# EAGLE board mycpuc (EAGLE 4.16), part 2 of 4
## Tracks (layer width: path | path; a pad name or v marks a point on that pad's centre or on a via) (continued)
+5V  (via drill 0.3 pad 0.3, 0.3 pad 0.81) (continued)
  Bottom 0.254: 153.55,53.21 R86.1 | 156,54.54 156,54.56 | 156,54.54 R85.1 | 156,53.21 156,54.54 | 157.5,60.01 155.95,60.01 155.95,60.03 R88.1 157.5,60.03 | 157.5,62.56 155.95,62.56 155.95,62.51 R87.1 157.5,62.51 | 157.5,65.01 155.95,65.01 155.95,65.02 R89.1 157.5,65.02 | 157.5,67.51 155.95,67.51 R90.1 157.5,67.53 | 157.5,70.01 R91.1 157.5,70.02 | 147.65,72.26 147.63,72.28 R92.1 | 14.5,26.01 14.44,25.95 R47.1 | R48.1 19,24.51 19.05,24.56 | R46.1 18.96,22.1 18.98,22.08 19,22.06 | R44.1 19,19.61 18.96,19.65 | R42.1 | 18.98,23.31 14.43,23.31 R45.1 | 18.96,20.81 R43.1 | 18.95,18.31 14.46,18.31 R41.1 | 113.58,30.96 IC15.26 | 111.05,28.81 111.55,28.31 113.55,28.31 IC15.22 | v110.45,29.56 110.5,29.36 111.05,28.81 | IC15.23 113.58,29.01 112.3,29.01 112.1,28.81 111.05,28.81 | v88.9,45.06 88.6,44.76 88.6,40.56 89.1,40.06 89.1,39.01 R84.2 | J1.A30 7.8,84.3 7.8,84.31 | 7.8,84.31 R38.2 | J1.C30 7.8,84.3 7.8,84.31 | R52.2 6.71,78.42 6.3,78.01 4.7,78.01 4,78.71 4,82.96 J1.A30 | J1.A30 | J1.A30 | R67.1 113.55,91.81 113.52,91.84 R117.2 | R121.2 141.92,66.94 v141.55,67.31 | R123.2 143.33,59.98 v143.35,60.01 143.35,59.96 143.4,60.01 144.4,60.01 144.85,59.56 144.85,54.86 144.48,54.49 R124.2 | C103.2 114.35,67.86 114.34,67.87 | R145.2 116.15,83.31 | R144.2 118.72,83.29 118.7,83.31 118.68,83.29 | R141.2 97.9,81.21 98.25,81.56 | 92.7,78.91 v92.65,78.91 92.7,78.86 | v64.65,96.56 64.63,96.58 | 64.6,95.31 v64.65,95.36 | D25.2 62.98,95.28 63,95.26 63.05,95.31 | R116.2 68.34,96.46 69.45,96.46 69.75,96.76 69.85,96.76 v69.85,96.81
  Bottom 0.305: R67.1 113.52,84.84 115.05,83.31 116.15,83.31 | R145.2 118.68,83.29 | R142.2 98.93,82.84 98.25,82.16 98.25,81.56 | 97.9,81.21 96.75,81.21 96,80.46 94.25,80.46 92.7,78.91 | R143.2 92.36,78.52 92.7,78.86
  Bottom 0.35: IC16.26 89.6,10.45 89.75,10.46 91.85,10.46
  Bottom 0.406: 157.5,60.01 157.5,53.56 157.15,53.21 156,53.21 153.55,53.21 153.55,52.46 v153.6,52.41 153.65,52.36 | 157.5,60.03 157.5,62.56 | 157.5,62.51 157.5,65.01 | 157.5,65.02 157.5,67.51 | 157.5,67.53 157.5,70.01 | 157.5,70.02 157.5,71.31 157.05,71.76 150.85,71.76 149,73.61 148,73.61 147.65,73.26 147.65,72.26 | 16.65,26.01 18.8,26.01 19.05,25.76 19.05,24.56 | 16.65,26.01 14.5,26.01 | 18.98,22.08 18.98,23.31 R48.1 | 18.96,19.65 18.96,20.81 R46.1 | R42.1 18.95,18.31 R44.1 | R102.1 120.86,12.85 120.85,13.01 118.35,13.01 | 105.65,13.01 103.25,13.01 103.1,12.86 103.1,11.56 R95.1 | 105.65,13.01 105.7,13.01 105.69,13 R96.1 | 108.2,13.01 110.75,13.01 | 110.75,13.01 113.25,13.01 | 113.25,13.01 115.8,13.01 | 115.8,13.01 118.35,13.01 | R97.1 108.19,13 108.2,13.01 | R98.1 110.74,13 110.75,13.01 | R99.1 113.24,13 113.25,13.01 | R100.1 115.79,13 115.8,13.01 | R101.1 118.36,13 118.35,13.01 | J1.C8 15.13,28.42 16.65,26.91 16.65,26.01 | v16.4,60.01 14.75,60.01 C57.1 | 105.65,13.01 108.2,13.01 | 113.58,30.96 111,30.96 110.45,30.41 v110.45,29.56 | J10.20 | 92.35,8.51 92.35,8.11 92.08,7.84 IC16.22 89.59,7.84 87.46,7.84 v86.85,8.46 86.95,8.51 89.65,8.51 | 92.35,8.51 92.35,9.96 91.85,10.46 | IC16.23 89.6,8.51 89.65,8.51 | 89.65,8.51 92.35,8.51 | 141.5,67.26 v141.55,67.31 143.21,68.97 R83.2 | v142.1,96.76 142.35,96.76 142.13,96.78 | L6.2 68.2,67.76 68.23,67.73 | C61.1 67.57,69.93 67.55,69.91 67.6,69.86 | R134.2 136.12,11.33 136.1,11.31 R135.2 R136.2 | R136.2 133.7,11.31 | R136.2 R137.2 | R137.2 131.3,11.36 | R138.2 R137.2 | R138.2 128.95,11.31 | R138.2 126.62,11.33 126.6,11.31 R139.2 | 113.3,67.87 R151.2 | 113.3,67.87 114.34,67.87 | v118.15,68.31 118.15,68.81 117.4,69.56 113.8,69.56 113.3,69.06 113.3,67.87
  Bottom 0.406: IC24.8 113.62,65.58 113.3,65.56 113.3,67.87 | 64.63,96.58 64,97.21 63.1,97.21 D25.1 | v64.65,95.36 v64.65,96.56 | 63.05,95.31 64.6,95.31
  Bottom 0.61: 120.85,13.01 122.15,13.01 123.45,11.71 123.45,11.31 | 142.35,96.76 v143.1,96.76 | L3.2 142.13,96.78 | 123.45,11.31 J10.20 | 123.45,11.31 126.6,11.31
  Bottom 0.813: 68.23,67.73 L2.2 | L6.2 68.21,68.5 67.6,69.11 67.6,69.86 | v67.75,91.71 v68.55,91.71 v69.35,91.71 | v105.8,42.33 105.8,43.38 105.78,43.41 | 8.3,28.36 8.3,28.41 v8.3,30.76 | 7.2,28.41 v7.2,30.76 | J1.C8 10.42,28.41 10.4,28.41 12.15,28.41 v12.15,30.36
  Bottom 1.016: 68.15,67.81 68.18,67.78 L6.2 | R158.2 112.38,43.41 105.78,43.41
  Bottom 1.27: v67.75,91.71 64.95,88.91 64.95,78.01 66.35,76.61 66.35,74.16 65.45,73.26 65.45,68.51 66.15,67.81 68.15,67.81 | J1.C8 10.4,28.41 8.3,28.41 7.2,28.41 5.35,28.41
  other vias: 105.8,43.41
  pour Route15 (isolate 0.254): 0.2,0.41 0.25,9.11 0.25,99.66 18.15,99.66 18.15,38.26 18.85,37.61 19.85,37.61 19.85,35.16 15.65,31.01 15.65,14.91 41.65,14.91 41.65,16.11 48.35,16.11 48.35,9.06 74.2,9.06 74.2,20.18 87.3,33.28 87.3,91.16 67.15,91.16 62.4,95.91 50.15,95.91 50.2,95.91 18.55,95.91 18.55,99.66 159.75,99.66 159.8,0.41
-5V
  Bottom 0.254: 108.24,91.62 108.25,91.61 | 108.24,91.62 R67.3 | 108.32,91.69 108.24,91.62 | 105.45,88.91 D26.A
  Bottom 0.305: C85.1 105.34,91.72 105.45,91.56 105.45,88.91 | D26.A 105.53,88.94 105.45,88.91 | R148.1 105.45,88.91
  Bottom 0.406: C85.1 108.32,91.69
-10V  (via drill 0.3 pad 0.81)
  Top 0.254: D14.2 108.93,31.13 108.9,31.16 D14.1 108.8,31.46 107.65,32.61 107.65,33.06 107.48,33.29 D15.1 105.52,33.29 105.51,33.3 | 105.51,33.3 105.8,33.36 105.55,33.36 105.55,34.31 103.25,36.61 98.05,36.61 v97.8,36.91 | 105.51,33.3 D15.2
  Bottom 0.254: v97.8,36.91 97.8,36.86
  Bottom 0.305: v97.8,36.91 97.8,53.96 99.65,55.81 99.65,60.51 103.65,64.51 103.65,76.96 104.3,77.61 105.7,77.61 106.2,78.11 106.2,79.96 105.45,80.71 R148.2
/B_WR
  Bottom 0.254: 10.42,33.49 10.45,33.46 | 10.42,33.49 J1.C10 | 10.42,33.49 10.43,33.49 10.8,33.86 10.85,33.86 11,34.01 12.45,34.01 12.48,34.04 R49.2
/BUS_RDC
  Top 0.254: IC9.6 13.43,34.74 10.9,32.21 6.5,32.21 5.3,31.01 J1.A9
/BUS_RDD  (via drill 0.3 pad 0.81)
  Top 0.254: J1.C9 10.64,30.96 10.65,30.96 13.78,34.09 IC9.7 | v98.25,57.01 98.25,56.76 101.2,53.81 102.45,53.81 103.3,54.66 IC23.11
  Route15 0.203: v98.25,57.01 97,57.01 94.7,59.31 94.7,64.51 82.8,76.41 49.1,76.41 48.15,75.46 42.85,75.46 42.75,75.51 25.2,75.51 18.35,68.66 15.55,68.66 14.45,67.56 14.45,40.76 11.05,37.36 9.75,37.36 9.15,36.76 9.15,32.26 10.46,30.96 J1.C9
/BUS_WR  (via drill 0.3 pad 0.81)
  Top 0.254: IC9.8 15,33.46 v16.3,33.46
  Bottom 0.254: R49.1 15.72,34.04 v16.3,33.46 16.32,33.44 R146.1
/INT.RES  (via drill 0.3 pad 0.81)
  Top 0.254: v17.45,85.11 16.2,85.11 12.9,81.81 10.5,81.81 10.45,81.76 10.44,81.76 J1.C29 | IC23.99 107.03,62.73 106.8,62.96 104.65,62.96 v104.25,62.56
  Route15 0.203: v17.45,85.11 17.45,85.16 23,85.16 23.45,85.61 37.45,85.61 42.3,90.46 48.25,90.46 49,89.71 62.65,89.71 65.75,86.61 76.8,86.61 80.85,82.56 85.65,82.56 102.75,65.46 102.75,64.01 v104.25,62.56
  Bottom 0.254: J1.C29 10.44,81.76 10.45,81.76 9.01,80.32 R52.1 | v17.45,85.11 22.75,85.11 24.55,86.91 35.95,86.91 36.5,87.46 36.5,90.16 37.19,90.85 T1.3
A0  (via drill 0.3 pad 0.81)
  Top 0.203: IC7.10 13.69,43.15 13.35,42.81 13.35,40.21
  Top 0.254: 13.35,40.21 11.75,38.61 10.4,38.61 J1.C12 | v96.9,58.41 98.2,58.41 100.95,55.66 IC23.9
  Route15 0.203: J1.C12 10.45,38.56 13.75,41.86 13.75,67.96 15.1,69.31 17.95,69.31 24.9,76.26 41.1,76.26 42.85,78.01 48.25,78.01 49.1,77.16 83.15,77.16 95.5,64.81 95.5,59.81 v96.9,58.41
A1  (via drill 0.3 pad 0.81)
  Top 0.203: IC7.9 13.54,43.8 12.8,43.06 12.8,40.91 11.75,39.86
  Top 0.254: J1.A12 6.6,39.86 11.75,39.86 | IC23.8 101.7,56.16 v101.25,56.61
  Route15 0.203: 5.35,38.57 5.35,38.56 | J1.A12 5.35,38.57 | 5.35,38.57 5.35,38.61 7.05,40.31 7.05,41.56 7.3,41.81 7.3,75.56 9.7,77.96 13.9,77.96 16.75,80.81 22.35,80.81 24.8,83.26 38.25,83.26 43.6,88.61 47.15,88.61 47.9,87.86 61.35,87.86 64.85,84.36 75.9,84.36 79.85,80.41 84.45,80.41 99.2,65.66 99.2,63.46 99.8,62.86 99.8,58.11 101.25,56.66 v101.25,56.61
A2  (via drill 0.3 pad 0.81)
  Top 0.203: IC7.8 13.34,44.45 12.25,43.36 12.25,41.91 11.5,41.16
  Top 0.254: J1.C13 10.4,41.16 11.5,41.16 | IC23.6 102.75,57.16 v102.65,57.26
  Route15 0.203: J1.C13 10.4,41.11 | J1.C13 | J1.C13 11.7,42.41 11.7,72.26 12.5,73.06 18.25,73.06 25.7,80.51 47.65,80.51 48.9,81.76 60,81.76 60.4,82.16 74.95,82.16 78.8,78.31 83.15,78.31 96.45,65.01 96.45,60.21 100.95,55.71 101.95,55.71 102.65,56.41 v102.65,57.26
A3  (via drill 0.3 pad 0.81)
  Top 0.203: IC7.7 13.09,45.1 11.7,43.71 11.7,43.06 11.1,42.46
  Top 0.254: J1.A13 5.35,41.11 6.7,42.46 11.1,42.46 | IC23.4 102.5,58.16 v101.35,59.31
  Route15 0.203: J1.A13 5.35,41.11 6.65,42.41 6.65,77.53 9.6,80.46 13.1,80.46 14.2,81.56 21.95,81.56 24.45,84.06 37.95,84.06 43.1,89.21 47.55,89.21 48.3,88.46 61.85,88.46 65.2,85.11 76.25,85.11 80.2,81.16 84.8,81.16 101.25,64.76 101.25,59.41 v101.35,59.31
A4  (via drill 0.3 pad 0.76, 0.3 pad 0.81)
  Top 0.254: IC23.97 108.03,62.58 106.9,63.71 103.2,63.71 101.85,62.36 v98.55,62.36 | v16.5,45.48 16.5,45.51 16.26,45.75 IC7.6
  Route2 0.254: v8.88,47.41 8.97,47.51 14.47,47.51 v16.5,45.48
  Route15 0.203: v98.55,62.36 98.35,62.56 98.35,65.36 84.05,79.66 79.6,79.66 75.6,83.66 64.5,83.66 60.9,87.26 48.95,87.26 47.3,85.61 41.85,85.61 38.65,82.41 25.1,82.41 20.4,77.71 16.05,77.71 13.8,75.46 9.75,75.46 7.95,73.66 7.95,48.36 8.88,47.43 v8.88,47.41
  Bottom 0.254: R147.2 8.26,46.99 8.68,47.41 v8.88,47.41
A4B
  Bottom 0.254: R147.1 8.26,43.35 8.47,43.13 10.12,43.13 10.47,43.48 10.43,43.68 10.44,43.66 | 10.44,43.66 10.45,43.66 | 10.44,43.66 J1.C14
A5  (via drill 0.3 pad 0.81)
  Top 0.254: IC7.5 12.34,46.4 10.85,44.91 6.6,44.91 5.36,43.66 J1.A14 | IC23.22 103,49.16 101.9,48.06 99.9,48.06 97.8,50.16 97.8,55.66 92.95,60.51 v92.95,60.96
  Route15 0.203: v92.95,60.96 92.95,63.96 81.85,75.06 66.9,75.06 65.6,73.76 52.6,73.76 49.2,70.36 40.25,70.36 37.15,67.26 37.15,65.76 36.15,64.76 26.15,64.76 25,63.61 25,56.61 20.55,52.16 20.55,36.16 13.55,29.21 11.65,29.21 11.1,29.76 4.5,29.76 3.7,30.56 3.7,41.98 5.33,43.61 5.34,43.62 J1.A14
A6
  Top 0.254: IC7.4 11.84,47.05 11,46.21 10.45,46.21 10.45,46.2 J1.C15
A7
  Top 0.203: 9.05,48.48 10.03,47.51
  Top 0.254: IC7.3 11.49,47.7 11.3,47.51 10.03,47.51 | J1.A15 7.65,48.48 9.05,48.48
A8  (via drill 0.3 pad 0.81)
  Top 0.203: IC8.10 13.81,54.17 13.4,53.76 13.4,51.61 10.55,48.76 10.45,48.76
  Top 0.254: 10.45,48.76 10.44,48.74 J1.C16 | IC23.3 103.45,58.66 101.6,60.51 v97.45,60.51
  Route15 0.203: v97.45,60.51 97.45,65.11 83.65,78.96 79.25,78.96 75.25,82.96 64.15,82.96 60.45,86.66 49.55,86.66 48.1,85.21 48.1,83.66 47.4,82.96 40.45,82.96 39.1,81.61 25.5,81.61 17.7,73.81 12.2,73.81 11.3,72.91 9.5,72.91 8.6,71.96 8.6,50.56 10.2,48.96 10.43,48.76 J1.C16
A9  (via drill 0.3 pad 0.81)
  Top 0.203: IC8.9 13.66,54.82 12.8,53.96 12.8,51.91 10.95,50.06 10.9,50.06
  Top 0.254: J1.A16 6.65,50.06 10.9,50.06 | IC23.1 103.55,59.66 102.8,60.41 v102.8,60.86
  Route15 0.203: J1.A16 3.9,50.21 3.9,82.56 4.35,83.01 12.55,83.01 13.7,84.16 23.35,84.16 24.05,84.86 37.7,84.86 42.7,89.86 47.9,89.86 48.7,89.06 62.3,89.06 65.55,85.81 76.6,85.81 80.55,81.86 85.25,81.86 101.95,65.16 101.95,61.71 v102.8,60.86
A10
  Top 0.203: IC8.8 13.51,55.47 12.2,54.16 12.2,52.66 10.85,51.31 10.45,51.31
  Top 0.254: 10.45,51.31 J1.C17
A11
  Top 0.203: IC8.7 13.36,56.12 11.65,54.41 11.65,53.26 10.95,52.56 10.9,52.56
  Top 0.254: J1.A17 6.6,52.56 10.9,52.56
A12
  Top 0.203: IC8.6 13.21,56.77 10.45,54.01
  Top 0.254: 10.43,53.82 10.45,53.81 | J1.C18 10.43,53.82 | 10.43,53.82 10.45,54.01
A13
  Top 0.203: IC8.5 13.06,57.42 10.75,55.11 10.7,55.11
  Top 0.254: J1.A18 5.35,53.81 6.65,55.11 10.7,55.11
A14
  Top 0.254: IC8.4 12.66,58.07 10.95,56.36 10.45,56.36 10.44,56.36 J1.C19
A15
  Top 0.254: IC8.3 12.26,58.72 11.2,57.66 6.65,57.66 J1.A19
ADDR0  (via drill 0.3 pad 0.76, 0.3 pad 0.81)
  Top 0.203: 41.02,80.98 41.02,80.99 IC10.1
  Top 0.254: IC21.P15 51.99,44.75 50.45,43.21 50.45,41.96 47.1,38.61 46.6,38.61 46.57,38.58 J4.21 | IC7.14 18.94,42.5 v18.75,42.31 | IC11.1 41,96.06 40.87,95.93 40.87,89.81 41.83,88.86 41.83,84.18 41.02,82.98 41.02,80.98 41.02,76.73 42.35,75.41 42.35,66.46 v41.65,65.76
  Route2 0.203: 41.8,65.61 v41.65,65.76 | J4.21 46.58,38.61 46.7,38.61
  Route2 0.254: 41.8,65.61 42.2,65.16 42.2,63.41 42.9,62.71 48.1,62.71 51.6,59.21 51.6,44.71 50.4,43.51 50.4,42.31 46.7,38.61
  Route15 0.254: v38.95,38.06 38.95,38.01 39,37.96 40.7,37.96 41.05,38.31 42.25,38.31 43.25,37.31 44.85,37.31 46.1,38.56 46.55,38.56 J4.21
  Bottom 0.203: IC12.45 34.88,68.74 35.7,69.56 37.95,69.56 41.65,65.86 v41.65,65.76
  Bottom 0.254: v38.95,38.06 37.8,39.21 22.4,39.21 19.3,42.31 v18.75,42.31
ADDR1  (via drill 0.3 pad 0.76, 0.3 pad 0.81)
  Top 0.152: 40.4,84.01 40.4,87.26 | 40.4,69.26 40.4,72.41
  Top 0.203: IC7.15 20.29,43.15 20.25,43.11 v17.65,43.11 | 40.4,84.01 39.75,83.01 39.75,82.28 | 39.75,80.98 | 39.75,80.98 IC10.2 | 39.75,82.28 39.75,80.98 | 39.75,82.28 39.75,76.21 40.4,75.21 40.4,72.41 | v41.1,64.71 41.1,64.96 40.8,65.26 40.8,68.51 40.4,69.26
  Top 0.254: IC21.P14 51.49,45.25 49.65,43.41 49.65,42.26 47.25,39.86 45.95,39.86 44.7,38.61 43.95,38.61 43.98,38.58 J4.22 | IC11.2 39.75,89.66 40.4,89.01 40.4,87.26
  Route2 0.203: v21.8,62.46 21.8,60.96 16.7,55.86 v16.65,55.86
  Bottom 0.203: v17.65,43.11 19.35,43.11 | 24.9,64.26 24.88,64.28 IC12.25 | v41.1,64.71 40.6,65.21 40.6,66.01 37.7,68.91 35.85,68.91 35.4,68.46 35.4,67.66 37.4,65.66 37.4,62.31 37,61.91 30.75,61.91 27.8,58.96 | v21.8,62.46 22.05,62.41
  Bottom 0.254: J4.22 44,38.61 43.9,38.71 43.4,39.16 42.75,39.16 42.1,39.81 22.65,39.81 19.35,43.11 | v17.65,43.11 17.05,43.11 15.57,44.58 15.57,54.78 v16.65,55.86 | 27.8,58.96 26.95,58.96 24.9,61.01 24.9,62.41 | 22.05,62.41 24.9,62.41 | 24.9,62.41 24.9,64.26
ADDR2  (via drill 0.3 pad 0.76, 0.3 pad 0.81)
  Top 0.152: 39.12,84.01 39.12,87.28 | 39.1,69.31 39.1,72.41
  Top 0.203: IC7.16 18.86,43.8 v18.75,43.91 | 39.12,84.01 38.48,83.01 38.48,81.01 38.48,81 | 38.48,81 38.5,80.98 | 38.48,81 IC10.3 | 38.48,81 38.48,76.03 39.1,75.01 39.1,72.41 | v38.9,63.96 38.9,64.26 39.7,65.06 39.7,68.31 39.1,69.31
  Top 0.254: IC21.P13 50.99,45.75 48.8,43.56 48.8,42.86 47.05,41.11 47.04,41.12 J4.23 | IC11.3 38.48,89.65 39.12,89.01 39.12,87.28 | IC7.16 22.94,43.8 v24,44.86
  Route2 0.203: 38.9,63.76 v38.9,63.96 | 46.65,41.16 46.61,41.12 J4.23
  Route2 0.254: 38.9,63.76 42.35,60.31 49.3,60.31 50.75,58.86 50.75,45.01 49.5,43.76 49.5,42.66 48,41.16 46.65,41.16
  Bottom 0.203: 24.88,44.83 IC12.24
  Bottom 0.254: J4.23 45.39,39.96 43.1,39.96 42.65,40.41 22.9,40.41 19.4,43.91 v18.75,43.91 | v24,44.86 24.88,44.83
ADDR3  (via drill 0.3 pad 0.76, 0.3 pad 0.81)
  Top 0.152: 37.85,84.01 37.85,87.28 | 37.85,69.11 37.85,72.41
  Top 0.203: v17.65,44.46 17.9,44.71 19.1,44.71 19.36,44.45 IC7.17 20.94,44.45 20.95,44.46 22.45,44.46 25.1,47.11 v25.1,47.26 | 37.85,84.01 37.23,82.98 37.23,81.03 | 37.23,81.03 37.21,81 IC10.4 | 37.23,81.03 37.2,80.96 37.33,80.83 37.33,75.83 37.85,74.96 37.85,72.41 | v38.35,66.96 38.4,66.96 38.1,67.21 38.1,68.61 37.85,69.11
  Top 0.254: IC21.P12 50.49,46.25 48,43.76 48,43.11 47.3,42.41 46.05,42.41 44.7,41.06 44.1,41.06 44.04,41.12 J4.24 | IC11.4 37.21,89.67 37.85,89.01 37.85,87.28
  Route2 0.203: J4.24 44.09,41.12
  Route2 0.254: v38.35,66.96 41.75,66.96 43.5,65.21 47.8,65.21 48.3,64.71 48.3,63.86 52.45,59.71 52.45,45.11 53.45,44.11 53.45,42.11 48.6,37.26 45.9,37.26 45.3,37.86 45.3,39.91 44.09,41.12
  Bottom 0.203: v17.65,44.46 17.9,44.71 19.45,44.71 | IC12.23 25.38,46.99 v25.1,47.26
  Bottom 0.254: 19.45,44.71 23.14,41.02 43.84,41.02 44,41.06 44.01,41.07 J4.24
ADDR4  (via drill 0.3 pad 0.76, 0.3 pad 0.81)
  Top 0.152: 36.58,84.01 36.58,87.31 | 36.6,69.11 36.6,72.38
  Top 0.203: v18.75,45.51 19.1,45.51 19.51,45.1 IC7.18 20.86,45.1 20.9,45.06 22.3,45.06 24.25,47.01 24.25,47.56 24.95,48.26 25.5,48.26 v25.65,48.36 | 36.58,84.01 35.95,83.01 IC10.5 | IC10.5 | IC10.5 | IC10.5 35.95,81.01 36.15,80.81 36.15,79.31 36.25,79.21 36.25,75.61 36.6,75.01 36.6,72.38 | 36.6,69.11 37,68.41 37,66.06 34.85,63.91 34.85,63.26
  Top 0.254: J4.25 46.9,43.66 49.99,46.75 IC21.P11 | IC11.5 35.94,89.64 36.58,89.01 36.58,87.31 | v34.8,63.21 34.85,63.26
  Route2 0.203: J4.25 46.55,43.71
  Route2 0.254: v34.8,63.21 34.8,62.71 40.05,57.51 47.3,57.51 47.85,56.96 47.85,45.01 46.55,43.71
  Bottom 0.203: IC12.22 25.88,48.19 v25.65,48.36
  Bottom 0.254: J4.25 45.3,42.41 43.05,42.41 42.25,41.61 23.4,41.61 19.5,45.51 v18.75,45.51
ADDR5  (via drill 0.3 pad 0.76, 0.3 pad 0.81)
  Top 0.152: 25.15,84.01 25.15,87.31
  Top 0.203: v17.65,46.56 17.9,46.31 19.2,46.31 19.76,45.75 IC7.19 20.89,45.75 20.9,45.76 22.25,45.76 23.65,47.16 23.65,48.06 v24.7,49.11 | 25.15,84.01 24.5,83.01 24.5,81.01 | 24.5,81.01 IC10.14 | 24.5,81.01 24.5,75.96 25.15,74.96 v25.15,72.81
  Top 0.254: IC21.P10 49.49,47.25 47.2,44.96 46.05,44.96 44.7,43.61 44,43.61 44.01,43.62 J4.26 | IC11.14 24.51,89.65 25.15,89.01 25.15,87.31
  Route2 0.203: v25.15,72.81 25.15,72.76 23.55,72.76 18.35,67.56 18.35,64.91 19.35,63.91 19.35,60.16 16.7,57.51 16.1,57.51 15.2,56.61 15.2,55.21 16.05,54.36 17.8,54.36 20.2,51.96 20.2,50.93 22.12,49.01 24.55,49.01 24.65,49.11 v24.7,49.11
  Bottom 0.203: v17.65,46.56 17.9,46.31 19.55,46.31 | IC12.21 26.38,47.79 26.5,47.91 26.5,48.81 26.1,49.21 | v24.7,49.11 24.8,49.21
  Bottom 0.254: J4.26 43.25,43.66 41.8,42.21 23.65,42.21 19.55,46.31 | 24.8,49.21 26.1,49.21
ADDR6  (via drill 0.3 pad 0.76, 0.3 pad 0.81)
  Top 0.152: 23.9,84.01 23.9,87.26 | 23.85,72.43 23.85,69.61 24.3,69.16
  Top 0.203: v18.75,47.11 18.8,47.06 19.2,47.06 19.86,46.4 IC7.20 20.81,46.4 20.8,46.41 22.15,46.41 23.1,47.36 23.1,49.26 23.7,49.86 v23.8,49.86 | 23.9,84.01 23.23,83.01 23.23,81.01 | 23.23,81.01 IC10.15 | IC10.15 | 23.23,81.01 23.23,75.88 23.85,74.86 23.85,72.43 | 24.3,69.16 24.3,64.96 v24,64.66
  Top 0.254: J4.27 46.89,46.2 48.94,48.25 IC21.P8 | IC11.15 23.24,89.69 23.9,89.03 23.9,87.26
  Route2 0.203: v24,64.66 24,68.76 23.45,69.31 20.95,69.31 18.9,67.26 18.9,65.21 19.95,64.16 19.95,59.91 16.95,56.91 16.3,56.91 15.8,56.41 15.8,55.46 16.3,54.96 18.15,54.96 20.85,52.26 20.85,51.13 22.27,49.71 23.6,49.71 v23.8,49.86
  Bottom 0.203: IC12.20 26.88,47.44 27.05,47.61 27.05,49.11 26.15,50.01
  Bottom 0.254: J4.27 45.31,44.96 43.5,44.96 41.35,42.81 23.9,42.81 19.6,47.11 v18.75,47.11 18.7,47.11 | v23.8,49.86 23.95,50.01 26.15,50.01
ADDR7  (via drill 0.3 pad 0.76, 0.3 pad 0.81)
  Top 0.152: 22.62,84.01 22.62,87.31 | 22.6,68.86 22.6,72.41
  Top 0.203: v17.65,47.91 19.1,47.91 19.96,47.05 IC7.21 20.76,47.05 20.75,47.06 22.05,47.06 22.55,47.56 22.55,50.21 v22.8,50.46 | 22.62,84.01 21.98,83.01 21.98,81.01 | 21.98,81.01 IC10.16 | 21.98,81.01 21.98,75.88 22.6,74.91 22.6,72.41
  Top 0.254: IC21.P7 48.44,48.75 47.15,47.46 45.95,47.46 44.7,46.21 44.1,46.21 44.09,46.2 J4.28 | IC11.16 21.97,89.66 22.62,89.01 22.62,87.31 | v22.95,68.51 22.6,68.86
  Route2 0.203: v22.95,68.51 21,68.51 19.5,67.01 19.5,65.41 20.15,64.76 20.85,64.76 22.75,62.86 22.75,61.06 21.5,59.81 21.5,51.36 22.4,50.46 v22.8,50.46
  Bottom 0.203: 24.15,43.41 41.1,43.41 43.89,46.2 | 43.89,46.2 43.85,46.21 | 43.89,46.2 J4.28 | v17.65,47.91 19.65,47.91 | 26.2,50.76 27.6,49.36 27.6,47.31 27.4,47.11 27.4,45.16 IC12.19
  Bottom 0.254: 19.65,47.91 24.15,43.41 | v22.8,50.46 23.1,50.76 26.2,50.76
ADDR8  (via drill 0.3 pad 0.76)
  Top 0.152: 21.32,84.01 21.32,87.31 | 21.35,69.16 21.35,72.41
  Top 0.203: 21.32,84.01 20.7,83.01 20.7,81.38 | IC10.17 20.7,75.81 21.35,74.81 21.35,72.41
  Top 0.254: J4.29 46.55,48.76 47.04,49.25 IC21.P6 | IC11.17 20.7,89.61 21.32,88.98 21.32,87.31 | 20.7,81.38 | IC10.17 20.7,81.38 | IC8.14 23.29,53.52 v29.1,47.71 | 21.35,69.16 21.35,67.91 v22.4,66.86
  Route2 0.203: 31.25,46.21 31.25,47.21 30.7,47.76 29.1,47.76 | v22.4,66.86 22.2,67.06 20.45,67.06 20.05,66.66 20.05,65.71 20.4,65.36 21.05,65.36 23.75,62.66 23.75,51.66 27.65,47.76 29.1,47.76 | 29.1,47.76 29.15,47.76 v29.1,47.71
  Route2 0.254: 31.25,46.21 31.65,45.81 38.8,45.81 40.6,47.61 45.45,47.61 46.55,48.71 J4.29
  Bottom 0.203: IC12.18 27.88,46.64 28.9,47.66 v29.1,47.71
ADDR9  (via drill 0.3 pad 0.76)
  Top 0.152: 20.07,84.01 20.07,87.36 | 20.05,69.21 20.05,72.41
  Top 0.203: 20.07,84.01 19.45,82.98 19.45,81.43 | IC8.15 26.89,54.17 31.95,49.11 31.95,46.96 v32.05,46.86 | IC10.18 19.43,75.73 20.05,74.71 20.05,72.41
  Top 0.254: IC21.P5 47.46,49.75 47.25,49.96 45.85,49.96 44.7,48.81 44.1,48.81 44.03,48.74 J4.30 | IC11.18 19.43,89.65 20.07,89.01 20.07,87.36 | 19.45,81.43 19.43,81.45 IC10.18 | 20.05,69.21 20.05,66.96 v20.85,66.21
  Route2 0.203: v20.85,66.21 21,66.21 24.3,62.91 24.3,51.96 25.9,50.36 30.85,50.36 31.95,49.26 31.95,46.91 32.05,46.81
  Route2 0.254: J4.30 40.63,48.74 38.7,46.81 32.05,46.81 v32.05,46.86
  Bottom 0.203: IC12.8 32.88,46.48 32.6,46.76 32.1,46.76 v32.05,46.86
ADDR10  (via drill 0.3 pad 0.76)
  Top 0.152: 20.07,79.53 20.07,82.98
  Top 0.203: IC11.20 20.7,84.03 20.07,82.98 | 20.07,79.53 20.07,75.81 20.7,74.81 20.7,70.81 20.7,67.46 21.7,66.46 21.7,65.76 21.35,65.41 20.4,65.41 18.95,63.96 18.95,62.86 17.7,61.01 17.7,56.81 19.7,54.81 20.8,54.81 20.81,54.82 IC8.16 27.04,54.82 32.8,49.06 v32.8,47.66
  Top 0.254: IC21.P4 48.21,50.25 47.15,51.31 46.6,51.31 46.57,51.28 J4.31 | 20.7,70.81 | 20.7,70.81 IC10.20
  Route2 0.254: J4.31 45.82,51.28 44.65,50.11 40.9,50.11 38.35,47.56 32.9,47.56 v32.8,47.66
  Bottom 0.203: IC12.7 33.38,47.08 v32.8,47.66
ADDR11  (via drill 0.3 pad 0.76)
  Top 0.152: 21.32,79.56 21.32,83.01
  Top 0.203: IC11.21 21.97,83.98 21.98,83.98 21.32,83.01 | 21.32,79.56 21.32,75.91 21.98,74.91 IC10.21 21.97,70.83 21.9,70.81 21.9,68.46 23.18,67.18 23.18,65.98 22.05,64.86 20.65,64.86 19.45,63.66 19.45,62.71 18.2,60.86 18.2,57.06 19.8,55.46 20.9,55.46 20.89,55.47 IC8.17 27.19,55.47 33.65,49.06 v33.65,48.36
  Top 0.254: IC21.P2 48.61,51.25 47.4,52.46 45.95,52.46 44.75,51.26 44.05,51.26 44.03,51.28 J4.32
  Route2 0.254: J4.32 41.02,51.28 38,48.26 33.75,48.26 v33.65,48.36 33.65,48.31
  Bottom 0.203: IC12.6 33.88,48.13 v33.65,48.36
ADDR12  (via drill 0.3 pad 0.76)
  Top 0.152: 22.6,79.58 22.6,83.01
  Top 0.203: IC11.22 23.24,84 22.6,83.01 | 22.6,79.58 22.6,75.91 23.23,74.91 23.23,70.91 23.25,70.88 | 23.25,70.88 IC10.22 | v34.55,49.11 34.35,49.11 27.34,56.12 IC8.18 20.89,56.12 | 23.25,70.88 23.25,69.41 23.75,68.91 23.75,65.71 22.35,64.31 20.85,64.31 19.95,63.41 19.95,62.51 18.7,60.66 18.7,57.31 19.8,56.21 20.8,56.21 20.89,56.12 | 20.89,56.12 20.9,56.11
  Top 0.254: IC21.P1 49.26,51.75 47.15,53.86
  Top 0.305: J4.33 46.55,53.86 47.15,53.86
  Route2 0.254: v34.55,49.11 34.55,49.06 | v34.55,49.11 37.75,49.11 41.25,52.61 45.25,52.61 46.5,53.86 46.55,53.86 J4.33 | v34.55,49.11 34.5,49.06
  Bottom 0.203: IC12.5 34.38,48.94 v34.55,49.11
ADDR13  (via drill 0.3 pad 0.76)
  Top 0.152: 23.9,79.61 23.9,83.01
  Top 0.203: IC11.23 24.51,84.02 23.9,83.01 | 23.9,79.61 23.9,75.81 24.35,75.06 24.35,70.83 | 24.35,70.83 24.51,70.84 IC10.23 | v35.35,49.91 34.35,49.91 27.49,56.77 IC8.19 20.81,56.77 20.8,56.76 20.75,56.81 19.95,56.81 19.2,57.56 19.2,60.46 20.45,62.31 20.45,63.11 21.15,63.81 24.4,63.81 24.85,64.26 24.85,69.36 24.5,69.71 24.5,70.11 | 24.35,70.83 24.35,70.36 24.6,70.11 24.5,70.11 | 24.5,70.11 24.45,70.11
  Top 0.254: IC21.P141 62.75,56.16 62.25,56.66 59.75,56.66 58.2,55.11 46,55.11 44.7,53.81 44.05,53.81 44.04,53.82 J4.34
  Route2 0.254: J4.34 41.41,53.82 37.45,49.86 35.35,49.86 v35.35,49.91
  Bottom 0.203: 34.88,48.09 IC12.4
  Bottom 0.254: 34.88,48.09 35.35,48.56 v35.35,49.91
ADDR14  (via drill 0.3 pad 0.76)
  Top 0.152: 25.15,79.63 25.15,83.01
  Top 0.203: IC11.24 25.78,84.01 25.15,83.01 | 25.15,79.63 25.15,76.06 25.95,74.86 25.95,70.86 25.75,70.86 IC10.24 25.78,68.74 25.4,68.36 25.4,63.96 24.7,63.26 21.4,63.26 20.95,62.81 20.95,62.16 19.7,60.26 19.7,57.81 20.05,57.46 20.85,57.46 IC8.20 27.64,57.42 34.3,50.76 v36.2,50.76
  Top 0.254: IC21.P140 63.25,56.66 62.55,57.36 59.35,57.36 58.35,56.36 46.6,56.36 46.55,56.41 J4.35
  Route2 0.254: J4.35 45.3,55.11 41.6,55.11 37.25,50.76 v36.2,50.76
  Bottom 0.203: 35.38,47.79 IC12.3
  Bottom 0.254: 35.38,47.79 36.2,48.61 v36.2,50.76
ADDR15  (via drill 0.3 pad 0.76, 0.3 pad 0.81)
  Top 0.152: 35.33,79.33 35.33,83.01
  Top 0.203: IC11.32 35.94,84 35.33,83.01 | IC10.32 35.92,70.88 35.95,71.26 36.02,71.33 36.02,74.91 35.75,75.38 35.75,78.91 35.33,79.33 | IC10.32 | IC8.21 21.3,58.06 21.39,58.02 27.85,58.02 | 27.85,58.02 34.09,51.77 35.26,51.77 35.3,51.81 v35.35,51.81 | 35.95,70.76 IC10.32 | v36.2,68.01 35.95,68.26 | 27.85,58.02 27.85,58.06 28.25,58.46 v28.55,58.46
  Top 0.254: IC21.P137 64.75,56.21 62.9,58.06 58.9,58.06 58.45,57.61 v49,57.61 | 35.95,68.26 35.95,70.76
  Route2 0.254: v35.35,51.81 37.2,51.81 41.8,56.41 43.95,56.41 J4.36
  Bottom 0.203: 35.88,47.49 IC12.2 | J4.36 44.05,56.36 | 36.2,67.86 v36.2,68.01
  Bottom 0.254: v49,57.61 49,56.61 47.5,55.11 45.3,55.11 44.05,56.36 | 35.88,47.49 37.05,48.66 37.05,51.36 36.6,51.81 v35.35,51.81 | 36.2,67.86 38,66.06 38,61.81 37.35,61.16 31.25,61.16 v28.55,58.46
ADDR16  (via drill 0.3 pad 0.76)
  Top 0.152: 36.6,79.66 36.58,79.68 36.58,83.01
  Top 0.203: IC11.33 37.21,84.02 36.58,83.01 | IC10.33 | 35.65,62.51 35.65,63.71 37.5,65.56 37.5,68.56 37.15,69.21 37.15,70.61 IC10.33 | IC10.33 37.2,74.96 36.8,75.71 36.8,79.46 36.6,79.66
  Top 0.254: IC21.P135 65.75,56.31 63.3,58.76 48.65,58.76 47.45,57.56 42.7,57.56 | 35.65,62.51 40.6,57.56 42.7,57.56 | v41.15,45.41 42.7,46.96 42.7,57.56
  Bottom 0.203: v41.15,45.41 41.1,45.41
  Bottom 0.254: IC12.1 36.38,45.24 36.4,45.41 v41.15,45.41
ADDR17  (via drill 0.3 pad 0.76)
  Top 0.152: 37.85,79.63 37.85,83.01
  Top 0.203: IC11.34 38.48,84.01 37.85,83.01 | 37.85,79.63 37.85,76.01 38.48,75.01 38.48,70.98 IC10.34 | 38.5,70.86 38.5,69.26 39.18,68.08 39.18,65.69 v36.55,63.06
  Top 0.254: IC21.P132 67.25,55.86 63.55,59.56 48.7,59.56 48.05,60.21 39.4,60.21 v36.55,63.06 | 38.5,70.86 38.49,70.86 IC10.34
  Bottom 0.254: IC12.48 36.38,63.29 v36.55,63.06
ADDR18  (via drill 0.3 pad 0.76)
  Top 0.152: 39.12,79.66 39.12,83.01
  Top 0.203: IC11.35 39.75,84.01 39.12,83.01 | 39.12,79.66 39.12,76.01 39.75,75.01 39.75,71.03 39.73,71.01 39.75,70.98 IC10.35 39.75,69.31 40.25,68.41 40.25,64.01
  Top 0.254: IC21.P131 67.75,56.36 63.8,60.31 49.55,60.31 47.25,62.61 41.4,62.61 v40,64.01 | v40,64.01 40.25,64.01 | 40.25,64.01 | v40,64.01 | v30.05,58.41 30.05,57.06 v32,55.11
  Bottom 0.203: IC12.17 28.38,46.14 28.8,46.56
  Bottom 0.254: v30.05,58.41 32.1,60.46 37.75,60.46 40,62.71 v40,64.01 | 28.8,46.56 29.15,46.56 32,49.41 v32,55.11
BUS_4MHZ  (via drill 0.3 pad 0.81)
  Top 0.254: IC9.10 16.68,32.14 17.3,32.76 17.3,35.06 v16.75,35.61
  Bottom 0.254: v16.75,35.61 16.75,35.56 15.83,36.48 R51.1
BUS_CLK  (via drill 0.3 pad 0.81)
  Top 0.254: IC9.9 13.68,32.79 12.9,32.01 v12.9,31.66
  Bottom 0.254: R50.2 7.97,32.24 8.15,32.06 9.35,32.06 9.6,32.26 12.3,32.26 v12.89,31.67 v12.9,31.66
  Bottom 0.305: v12.9,31.66 12.9,31.71 v12.89,31.67
BUSCKOUT
  Bottom 0.254: R50.1 7.97,35.89 7.8,36.06 J1.A11
BUSCLK
  Top 0.254: IC9.15 42.98,32.14 43.15,32.31 44.7,32.31 45.89,33.5 | 45.89,33.5 46.6,33.51 | 45.89,33.5 J4.17 46.69,33.5 46.7,33.51 48.85,33.51 50.1,34.76 50.1,35.71 54.14,39.75 IC21.P25
BUSY
  Top 0.254: IC23.90 111.53,66.73 103.85,74.41 102.25,74.41 101.15,75.51 101.15,77.56 99.89,78.82 J15.21
  Bottom 0.254: J15.21 99.82,78.84 R141.1
C_TCK  (via drill 0.3 pad 0.81)
  Top 0.254: IC23.48 117.53,53.18 v114,56.71
  Route15 0.254: J14.5 72.8,92.96 72.8,90.76 73.55,90.01 75.1,90.01 81.3,83.81 95.85,83.81 99.3,80.36 103,80.36 103.65,79.71 103.65,75.21 105.45,73.41 105.45,65.41 110.05,60.81 110.05,55.71 111.8,53.96 112.75,53.96 114.05,55.26 114.05,56.66 v114,56.71
C_TDI  (via drill 0.3 pad 0.81)
  Top 0.254: v112.25,54.86 112.3,54.86 116.03,51.13 IC23.45
  Route15 0.254: J14.4 75,90.76 75.5,90.76 81.6,84.61 97.4,84.61 100.6,81.41 104.4,81.41 106.2,79.61 106.2,65.66 110.85,61.01 110.85,56.61 112.2,55.26 112.2,54.81 | 112.2,54.81 112.2,54.76 | v112.25,54.86 112.2,54.81
C_TDO  (via drill 0.3 pad 0.81)
  Top 0.254: IC23.83 115.03,62.98 114.7,63.31 114.7,70.41 v114.45,70.66
  Route15 0.254: J14.6 70.05,93.16 70.05,95.06 70.6,95.61 74.7,95.61 75.25,95.06 75.25,93.66 75.9,93.01 77.55,93.01 78.25,92.31 78.25,90.26 82.15,86.36 99,86.36 101.7,83.66 107.25,83.66 111.25,79.66 111.25,73.91 114.5,70.66 v114.45,70.66
C_TMS  (via drill 0.3 pad 0.81)
  Top 0.254: IC23.47 117.03,51.88 v113.1,55.81
  Route15 0.254: J14.2 76.57,90.84 81.85,85.51 97.4,85.51 100.4,82.51 105.8,82.51 108.7,79.61 108.7,75.26 107,73.56 107,65.91 111.6,61.31 111.6,57.06 112.85,55.81 v113.1,55.81
CLK
  Top 0.254: IC21.P52 68.75,28.01 68.3,27.56 55.4,27.56 54.9,27.06 54.9,24.81 55.45,24.26 58.95,24.26 59.4,23.81 59.4,23.36 59.44,23.3 JP1.2
CLK4MHZ  (via drill 0.3 pad 0.81)
  Top 0.254: v88.9,46.36 88.8,46.61 88.42,46.99 IC14.14 | IC21.P26 54.74,39.25 51.45,35.96 v51.45,35.41 51.45,35.01 48.65,32.21 46,32.21 45.3,31.51 45.3,30.36 44.6,29.66 43.05,29.66 41.22,31.49 IC9.14
  Bottom 0.254: v88.9,46.36 88.75,46.36 87.75,45.41 87.75,36.31 90.05,34.01 90.05,32.46 85.95,28.41 85.75,28.21 84.85,28.21 82.55,25.91 74.2,25.91 71.7,23.41 71.7,18.41 69.1,15.76 67.9,15.76 65.25,13.11 65.25,12.41 62.75,9.91 54.45,9.91 51.25,13.11 51.25,35.16 51.4,35.31 51.4,35.41 | J4.52 44.03,76.68 45.35,77.96 47.5,77.96 47.9,77.56 52.85,77.56 56.25,74.21 56.25,40.26 51.4,35.41 | v51.45,35.41 51.4,35.41
D0  (via drill 0.3 pad 0.81)
  Top 0.254: IC6.10 13.77,21.18 10.85,18.26 10.45,18.26 10.44,18.26 J1.C4 | v101.5,49.01 101.8,49.01 102.95,50.16 IC23.20
  Route15 0.203: v101.5,49.01 101.55,49.01 101.25,48.76 97.5,48.76 86.75,59.51 86.75,60.41 78.7,68.46 71.3,68.46 70.75,67.91 61.7,67.91 52.05,58.26 52.05,55.81 48.6,52.36 48.6,51.11 47.5,50.01 41.8,50.01 37.2,45.41 37.2,37.06 32.4,32.26 30,32.26 21.05,23.26 16.15,23.26 11.15,18.26 10.45,18.26 10.44,18.26 J1.C4
  Bottom 0.254: R41.2 12.54,18.26 J1.C4
D1  (via drill 0.3 pad 0.81)
  Top 0.254: IC6.9 13.37,21.83 11.1,19.56 6.6,19.56 5.34,18.3 J1.A4 | IC23.18 103,51.16 101.8,49.96 100.75,49.96 v100.45,49.66
  Route15 0.203: v100.45,49.66 100.35,49.56 97.55,49.56 87.55,59.56 87.55,60.41 78.75,69.21 71,69.21 70.35,68.56 61.2,68.56 51.2,58.61 51.2,56.26 47.45,52.56 43.35,52.56 36.5,45.71 36.5,37.26 32.2,32.96 29.7,32.96 20.9,24.11 15.85,24.11 11.3,19.56 8.55,19.56 7.25,18.26 J1.A4
  Bottom 0.254: J1.A4 6.79,18.26 8.05,17.01 17.04,17.01 R42.2
D2  (via drill 0.3 pad 0.81)
  Top 0.254: IC6.8 12.97,22.48 11.3,20.81 10.45,20.81 10.45,20.8 J1.C5 | IC23.17 102.6,51.66 101.55,50.61 99.55,50.61 v99.3,50.36
  Route15 0.203: v99.3,50.36 97.6,50.36 88.3,59.66 88.3,60.51 78.9,69.86 70.7,69.86 70.05,69.21 60.6,69.21 50.4,59.01 50.4,57.51 48.1,55.21 42.8,55.21 42.2,54.56 42.2,52.41 35.8,46.01 35.8,37.56 31.9,33.66 29.45,33.66 20.8,25.01 15.7,25.01 11.5,20.81 10.45,20.81 10.45,20.8 J1.C5
  Bottom 0.254: R43.2 12.55,20.81 12.55,20.8 J1.C5
D3  (via drill 0.3 pad 0.81)
  Top 0.254: IC6.7 12.57,23.13 11.55,22.11 6.65,22.11 J1.A5 | IC23.16 101.7,52.16 v101.1,51.56
  Route15 0.203: v101.1,51.56 101.1,51.51 100.9,51.31 97.55,51.31 89.05,59.81 89.05,60.61 77.9,71.71 71.55,71.71 69.7,69.86 60.15,69.86 49.65,59.36 48.75,59.36 48.15,58.76 48.15,58.16 47.6,57.61 42.95,57.61 41.35,56.06 41.35,52.56 35.1,46.31 35.1,39.86 33.9,38.66 33.9,38.06 33.05,37.21 33.05,35.81 31.55,34.31 29.15,34.31 20.6,25.81 15.4,25.81 11.65,22.06 8.55,22.06 7.3,20.81 5.4,20.81 5.4,20.8 J1.A5
  Bottom 0.254: J1.A5 6.8,20.8 8.05,19.56 R44.2
D4  (via drill 0.3 pad 0.81)
  Top 0.254: J1.C6 10.49,23.34 10.92,23.78 IC6.6 | IC23.15 100.45,52.66 v100.15,52.36
  Route15 0.203: v100.15,52.36 99.8,52.01 97.75,52.01 89.8,59.96 89.8,60.71 78.1,72.41 71.25,72.41 69.5,70.66 57.7,70.66 47.25,60.21 41.65,60.21 33.9,52.46 31.9,52.46 28.3,48.86 28.3,43.86 23.2,38.76 23.2,33.01 18.8,28.61 17.05,28.61 11.8,23.36 10.45,23.36 10.44,23.34 J1.C6
  Bottom 0.254: R45.2 12.55,23.36 12.54,23.34 J1.C6
D5  (via drill 0.3 pad 0.81)
  Top 0.254: IC6.5 12.68,24.43 12.45,24.66 6.65,24.66 J1.A6 | IC23.14 100.85,53.16 100.65,53.36 99.35,53.36 v98.95,52.96
  Route15 0.203: v98.95,52.96 97.65,52.96 90.6,60.01 90.6,60.71 78.25,73.06 68.1,73.06 66.45,71.41 57.35,71.41 48.65,62.71 43.2,62.71 33.65,53.16 31.65,53.16 27.7,49.21 27.7,44.21 22.55,39.06 22.55,33.36 18.5,29.31 16.75,29.31 12,24.56 8.75,24.56 7.55,23.36 5.33,23.36 | 5.33,23.36 5.25,23.36 | J1.A6 5.33,23.36
  Bottom 0.254: J1.A6 6.71,23.34 8,22.06 17,22.06 17.05,22.11 17.06,22.1 R46.2
D6  (via drill 0.3 pad 0.81)
  Top 0.254: IC6.4 13.08,25.08 12.25,25.91 10.45,25.91 J1.C7 | IC23.13 105.75,53.66 v106.2,53.21
  Route15 0.203: v106.2,53.21 106.15,53.16 100.6,53.16 99.85,53.91 97.55,53.91 91.3,60.16 91.3,60.81 78.35,73.71 67.65,73.71 66.15,72.21 56.95,72.21 49.95,65.21 43.15,65.21 42.4,64.46 42.4,62.91 33.35,53.86 31.35,53.86 27.1,49.61 27.1,44.61 21.85,39.36 21.85,35.46 12.3,25.91 10.5,25.91 10.45,25.86 J1.C7
  Bottom 0.254: R47.2 12.53,25.88 J1.C7
D7  (via drill 0.3 pad 0.81)
  Top 0.254: IC6.3 13.48,25.73 12.05,27.16 6.65,27.16 5.35,25.86 5.34,25.87 J1.A7 | IC23.12 105.85,54.16 v106.2,54.51
  Route15 0.203: J1.A7 5.35,25.91 7.35,25.91 8.5,27.06 12.4,27.06 21.2,35.86 21.2,39.66 26.5,44.96 26.5,50.06 30.75,54.31 30.75,55.41 37.85,62.51 37.85,64.31 41.35,67.81 51.55,67.81 56.7,72.96 65.85,72.96 67.25,74.36 81.5,74.36 92,63.86 92,60.31 97.85,54.46 100.15,54.46 100.8,53.81 102.6,53.81 103.3,54.51 v106.2,54.51 106.25,54.51
  Bottom 0.254: J1.A7 6.67,25.88 7.9,24.66 17.05,24.66 17.05,24.59 R48.2
DA0
  Top 0.254: J12.35 130.9,61.36 130.85,61.36 | 130.85,61.36 127.75,61.36 125.95,59.56 125.95,56.86 123.75,54.66 IC23.65 | J13.35 139.76,61.36 130.85,61.36
DA1
  Top 0.254: J12.33 130.95,57.56 130.95,57.66 130.92,58.86 130.9,58.86 | 130.9,58.86 127.75,58.86 127.15,58.26 127.15,56.36 124.45,53.66 IC23.63 | J13.33 139.77,58.86 130.9,58.86
DA2
  Top 0.254: IC23.64 124.1,54.16 126.55,56.61 126.55,58.71 127.95,60.11 128.23,60.08 J12.36
  Route15 0.254: J12.36 129.57,58.96 137.2,58.96 138.4,60.16 138.4,60.17 J13.36
DATA0  (via drill 0.3 pad 0.76)
  Top 0.152: 34.02,84.01 34.02,87.26
  Top 0.203: 34.02,84.01 33.38,83.01 33.38,80.98 | 33.38,80.98 33.4,81.01 IC10.7 | v24.05,37.71 24.05,38.76 | 37.1,53.71 27.75,63.06 27.75,65.81 26.75,66.81 v26.75,67.41 | 33.38,80.98 33.5,80.96 33.5,77.56 v33.55,77.36
  Top 0.254: IC21.P36 57.84,34.25 57.35,33.76 57.35,32.46 52.65,27.76 52.65,25.31 48.05,20.71 46.55,20.71 46.5,20.76 J4.7 46.6,20.76 45.4,19.56 42.4,19.56 41.43,20.53 IC6.14 | IC11.7 33.4,89.63 34.02,89.01 34.02,87.26 | 24.05,38.76 29.1,43.81 30.75,43.81 37.1,50.21 37.1,53.71
  Bottom 0.203: 26.75,67.56 26.63,67.59 v26.75,67.41 26.75,67.46 | 26.75,67.46 26.75,67.31 26.88,67.18 IC12.29 | 26.75,67.46 26.75,67.56 | 26.75,67.56 26.75,67.71 25.95,68.51 25.95,78.81 27.3,80.16 32.6,80.16 | 33.4,77.61 33.5,77.46 v33.55,77.36
  Bottom 0.254: v24.05,37.71 24.05,30.81 35.4,19.51 45.25,19.51 J4.7 | 32.6,80.16 33.4,79.36 33.4,77.61
DATA1  (via drill 0.3 pad 0.76)
  Top 0.152: 32.77,84.01 32.77,87.28 32.88,87.41
  Top 0.203: 32.77,84.01 32.12,83.01 32.12,81.01 | 32.12,81.01 32.13,81.01 IC10.8 | v24.85,36.96 24.85,38.66 | 37.75,53.81 28.3,63.26 28.3,66.06 27.9,66.46 27.9,67.06 v27.85,67.21 | 32.12,81.01 32.12,79.03 v32.25,78.91
  Top 0.254: IC21.P35 57.24,34.75 56.65,34.16 56.65,32.86 51.9,28.11 51.9,25.76 48.3,22.16 45.9,22.16 44.56,20.82 44.01,20.82 J4.8 43.96,20.8 43.58,21.18 IC6.15 | IC11.8 32.13,89.48 32.88,88.73 32.88,87.41 | 24.85,38.66 29.4,43.21 31.05,43.21 37.75,49.91 37.75,53.81
  Bottom 0.203: IC12.31 27.88,67.33 27.85,67.36 | 27.85,67.36 27.85,67.46 26.6,68.76 26.55,68.86 26.55,78.56 27.55,79.56 31.6,79.56 32.15,79.01 32.15,78.96 v32.25,78.91 | v27.85,67.21 27.85,67.36
  Bottom 0.254: v24.85,36.96 24.85,31.11 35.15,20.81 44.05,20.81 44.04,20.8 J4.8
DATA2  (via drill 0.3 pad 0.76)
  Top 0.152: 28.98,84.01 28.95,84.03 28.95,87.31 | 28.95,89.06 28.93,89.06 | 29.3,69.16 28.95,69.51 28.95,72.33
  Top 0.203: 28.95,87.31 28.95,89.06 | 28.98,84.01 28.32,83.01 28.32,81.08 IC10.11 28.35,80.96 28.3,80.91 28.3,79.51 28.12,79.33 28.12,77.09 28.95,75.81 28.95,72.33 | v25.65,37.71 25.65,38.56 | 38.35,53.96 28.85,63.46 v28.85,66.71 29.3,67.16 29.3,69.16
  Top 0.254: IC21.P33 57.24,35.75 55.95,34.46 55.95,33.21 51.15,28.41 51.15,26.21 48.3,23.36 46.55,23.36 J4.9 46.55,23.26 46.5,23.21 45.75,23.21 44.57,22.03 41.67,22.03 41.45,21.81 20.95,21.81 IC6.16 | IC11.11 28.32,89.66 28.93,89.06 | 25.65,38.56 29.7,42.61 31.4,42.61 38.35,49.56 38.35,53.96
  Bottom 0.203: v28.85,66.71 28.85,66.81 28.88,66.78
  Bottom 0.254: 28.88,66.78 IC12.33 | v25.65,37.71 25.65,31.26 34.85,22.06 45.35,22.06 46.55,23.26 J4.9
DATA3  (via drill 0.3 pad 0.76)
  Top 0.152: 27.7,84.01 27.7,87.31
  Top 0.203: 27.7,84.01 27.05,83.01 IC10.12 | IC10.12 | IC10.12 27.05,81.01 26.95,80.91 26.95,76.66 27.75,75.36 27.75,73.71 27.8,73.66 v27.75,73.66 | v26.45,36.96 26.45,38.51 | 38.95,54.11 29.9,63.16 29.9,66.26 29.85,66.31 v29.85,66.21 29.85,68.46 v30.2,68.81
  Top 0.254: IC21.P32 56.79,36.25 55.25,34.71 55.25,33.56 50.4,28.76 50.4,26.71 48.4,24.66 45.8,24.66 44.5,23.36 43.95,23.36 43.97,23.34 J4.10 43.92,23.34 43.9,23.36 41.8,23.36 40.92,22.48 IC6.17 | IC11.12 27.05,89.66 27.25,89.46 27.25,87.76 27.7,87.31 | 26.45,38.51 29.95,42.01 31.7,42.01 38.95,49.26 38.95,54.11
  Bottom 0.203: v29.85,66.21 29.88,66.29 29.9,66.31
  Bottom 0.254: 29.88,66.29 IC12.35 | v26.45,36.96 26.45,31.46 34.55,23.36 44,23.36 J4.10 | v30.2,68.81 27.75,71.26 v27.75,73.66
DATA4  (via drill 0.3 pad 0.76)
  Top 0.152: 26.43,79.63 26.43,83.01
  Top 0.203: IC11.25 27.05,84.01 26.43,83.01 | 26.43,79.63 26.43,76.36 26.95,75.51 26.95,70.96 27.05,71.01 IC10.25 27.05,69.56 v27.4,69.21 | v27.25,37.71 27.25,38.41 | 39.55,54.26 31.2,62.61 31.2,66.36 30.65,66.91 v30.65,67.16
  Top 0.254: IC21.P31 56.29,36.75 54.55,35.01 54.55,33.86 49.65,29.01 49.65,27.16 48.45,25.96 46.55,25.96 J4.11 46.47,25.88 46.45,25.86 45.85,25.86 44.6,24.61 41.85,24.61 40.37,23.13 IC6.18 | 27.25,38.41 30.25,41.41 32.05,41.41 39.55,48.91 39.55,54.26
  Bottom 0.203: 30.65,66.91 v30.65,67.16 29.65,67.16 28.8,68.01 28.1,68.01 27.4,68.71 v27.4,69.21
  Bottom 0.254: v27.25,37.71 27.25,31.61 34.35,24.56 45.25,24.56 46.55,25.86 J4.11 | IC12.38 31.38,66.18 30.65,66.91
DATA5  (via drill 0.3 pad 0.76)
  Top 0.152: 27.7,79.66 27.7,83.01
  Top 0.203: IC11.26 28.32,84 27.7,83.01 | 27.7,79.66 27.55,79.51 27.55,76.86 28.5,75.36 28.5,70.98 28.32,70.96 IC10.26 28.32,69.08 v28.5,68.81 | v28.05,36.96 28.05,38.31 | 40.15,54.41 31.85,62.71 31.85,67.11 v31.9,67.16
  Top 0.254: IC21.P30 55.79,37.25 53.85,35.31 53.85,34.21 48.9,29.31 48.9,27.66 48.45,27.21 45.8,27.21 44.46,25.87 J4.12 | J4.12 44,25.86 | J4.12 44.03,25.88 44.05,25.86 41.9,25.86 39.82,23.78 IC6.19 | 28.05,38.31 30.55,40.81 32.35,40.81 40.15,48.56 40.15,54.41
  Bottom 0.203: v28.5,68.81 28.85,68.81 29.7,67.96 31.1,67.96 v31.9,67.16
  Bottom 0.254: v28.05,36.96 28.05,31.91 34.65,25.26 43.4,25.26 J4.12 | IC12.40 32.38,66.68 v31.9,67.16
DATA6  (via drill 0.3 pad 0.76)
  Top 0.152: 31.5,77.21 31.5,83.01
  Top 0.203: IC11.29 32.13,84.01 31.5,83.01 | 32.33,70.98 32.13,70.98 IC10.29 32.2,70.86 32.35,71.16 32.35,72.21 33,72.86 33,75.71 31.5,77.21 | 40.75,54.56 32.5,62.81 32.5,66.16 32.75,66.41 32.75,67.61 v31.65,68.71
  Top 0.254: IC21.P28 55.79,38.25 53.15,35.61 53.15,34.56 48.1,29.51 48.1,28.81 47.7,28.41 J4.13 46.51,28.42 46.5,28.41 45.85,28.41 44.6,27.16 42,27.16 v41.8,26.96 39.27,24.43 IC6.20 | IC10.29 32.13,69.18 v31.65,68.71 | v33,38.31 33,40.56 40.75,48.31 40.75,54.56
  Bottom 0.203: IC12.42 33.38,66.93 31.65,68.66 v31.65,68.71
  Bottom 0.254: v33,38.31 33,27.96 34.95,26.01 40.9,26.01 41.85,26.96 v41.8,26.96
DATA7  (via drill 0.3 pad 0.76)
  Top 0.152: 32.75,79.61 32.75,83.01
  Top 0.203: IC11.30 33.4,84.01 32.75,83.01 | 32.75,79.61 33,79.36 33,78.26 32.65,77.91 32.65,77.01 33.6,76.06 33.6,70.96 | 33.15,69.38 33.15,69.16 | 33.15,69.38 33.4,69.61 33.4,70.71 33.44,70.82 | 33.44,70.82 33.6,70.96 | 33.6,70.96 33.6,70.91 | 33.4,67.71 33.4,68.06 33.15,68.31 33.15,69.38 | 41.35,54.71 33.15,62.91 33.15,65.96 33.4,66.21 33.4,67.71 | 33.4,67.71 v33.8,67.71 | 33.44,70.82 33.45,70.81 | 33.44,70.82 | IC10.30 33.44,70.82
  Top 0.254: IC21.P27 55.29,38.75 52.45,35.91 52.45,34.91 47.25,29.71 45.95,29.71 44.7,28.46 44,28.46 | IC6.21 20.97,25.08 21,25.11 37.85,25.11 v39.7,26.96 39.7,26.98 40.47,26.98 41.95,28.46 44,28.46 | 44,28.46 44.01,28.45 J4.14 | v33.95,37.01 33.95,40.56 41.35,47.96 41.35,54.71
  Bottom 0.203: IC12.44 34.38,67.13 v33.8,67.71
  Bottom 0.254: v33.95,37.01 33.95,28.16 35.15,26.96 v39.7,26.96
DD0
  Top 0.254: 130.9,38.56 J12.17 | 130.9,38.56 127.7,38.56 126.45,39.81 126.45,45.76 123.55,48.66 IC23.53 | 130.9,38.56 139.75,38.56 J13.17 143.7,40.06 143.7,41.51 145.5,43.31 147.15,43.31 147.5,43.66 147.5,44.61 147.53,44.64 R125.1
DD1
  Top 0.254: J12.15 130.91,36.01 130.85,36.01 | 130.85,36.01 127.05,36.01 120.35,42.71 | 118.55,45.56 118.55,45.66 IC23.50 118.55,45.64 118.55,45.56 | 118.55,44.51 118.55,45.11 | 118.55,44.51 120.35,42.71 | 118.55,45.56 118.55,44.51 | J13.15 139.76,36.01 130.85,36.01 | R126.1 121.48,43.84 120.35,42.71
DD2
  Top 0.254: 130.9,33.51 127.3,33.51 117.45,43.36 115.75,43.36 114.5,44.61 114.5,45.66 IC23.42 | J13.13 140.95,32.26 139.7,33.51 130.9,33.51 | 130.9,33.51 130.92,33.51 J12.13 130.95,32.21 130.91,32.25 R127.1
DD3
  Top 0.254: 130.9,30.96 130.9,30.86 | 130.9,30.86 130.89,29.67 J12.11 | 130.9,30.96 127,30.96 126.2,31.76 126.2,32.91 116.95,42.16 115.4,42.16 113.55,44.01 113.55,45.64 IC23.40 | J13.11 140.94,29.72 139.7,30.96 130.9,30.96 | 130.9,30.86 | 130.9,30.96 130.9,30.86 | J12.11 130.9,29.66 | R128.1 J12.11
DD4
  Top 0.254: 130.9,28.41 130.92,28.39 J12.9 130.95,27.16 R129.1 | IC23.37 112.03,43.88 114.95,40.96 116.45,40.96 125,32.41 125,30.16 126.75,28.41 130.9,28.41 | J13.9 139.75,28.41 130.9,28.41
DD5
  Top 0.254: 130.9,25.86 130.9,24.66 130.92,24.63 J12.7 | 130.9,25.86 127.4,25.86 123.8,29.46 123.8,31.91 115.95,39.76 114.55,39.76 111.05,43.26 111.05,45.66 IC23.35 | J13.7 139.75,25.86 130.9,25.86 | J12.7 130.9,24.56 J12.7 | J12.7 R130.1
DD6
  Top 0.254: 130.9,23.31 128.05,23.31 122.6,28.76 122.6,31.41 115.45,38.56 114.1,38.56 109.55,43.11 109.55,45.66 IC23.32 | J13.5 140.99,22.1 141,22.11 139.8,23.31 130.9,23.31 | 130.9,22.06 130.9,23.31 | 130.9,22.06 J12.5 | R131.1 130.94,22.02 130.9,22.06
DD7
  Top 0.254: 130.92,20.76 J12.3 130.95,19.51 130.96,19.5 R132.1 | IC23.29 108.05,45.66 108.05,43.01 113.7,37.36 114.95,37.36 121.4,30.91 121.4,28.11 126.4,23.11 126.4,21.81 127.45,20.76 130.92,20.76 | J13.3 140.95,19.56 139.75,20.76 130.92,20.76
DD8
  Top 0.254: IC23.28 107.55,45.64 107.55,42.71 113.5,36.76 114.7,36.76 120.8,30.66 120.8,27.76 125.75,22.81 125.75,21.16 127.4,19.51 J12.4 128.4,19.51 129.7,18.21 132.55,18.21 | J13.4 138.43,19.53 138.45,19.51 137.15,18.21 132.55,18.21 | R133.1 132.53,18.09 132.55,18.21
DD9  (via drill 0.3 pad 0.81)
  Top 0.254: J12.6 122,28.43 122,31.16 115.2,37.96 113.9,37.96 108.53,43.33 108.53,45.64 IC23.30
  Route15 0.254: J12.6 129.69,23.36 136.75,23.36 138,22.11 J13.6 138.43,21.78 138.55,21.66 139.7,20.53 139.7,15.91 138.5,14.71 138.5,14.66 v138.45,14.66
  Bottom 0.254: v138.45,14.66 138.5,14.66 138.45,14.61 R134.1
DD10  (via drill 0.3 pad 0.81)
  Top 0.254: J12.8 128.36,24.61 127.7,24.61 123.2,29.11 123.2,31.66 115.7,39.16 114.3,39.16 110.05,43.41 110.05,45.64 IC23.33
  Route15 0.254: J12.8 129.7,25.91 137.15,25.91 138.45,24.61 138.91,24.61 | 138.91,24.61 138.5,24.61 | 138.91,24.61 J13.8 | 138.91,24.61 140.11,23.41 141.95,23.41 142.65,22.71 142.65,15.96 139.85,13.11 137.4,13.11 136.05,14.41 136.1,14.56 136.1,14.66 v136.05,14.66
  Bottom 0.254: R135.1 136.08,14.63 v136.05,14.66
DD11  (via drill 0.3 pad 0.81)
  Top 0.254: J12.10 127.08,27.13 124.4,29.81 124.4,32.16 116.2,40.36 114.75,40.36 111.55,43.56 111.55,45.66 IC23.36
  Route15 0.254: J12.10 129.66,28.41 137.2,28.41 J13.10 | J13.10 138.45,27.16 | J13.10 138.48,27.18 139.65,28.36 143.15,28.36 145.4,26.11 145.4,16.36 140.5,11.51 135.95,11.51 133.7,13.76 v133.7,14.66
  Bottom 0.254: R136.1 v133.71,14.65 v133.7,14.66
DD12  (via drill 0.3 pad 0.81)
  Top 0.254: J12.12 127.34,29.67 125.6,31.41 125.6,32.66 116.7,41.56 115.15,41.56 113.05,43.66 113.05,45.66 IC23.39
  Route15 0.254: J13.12 138.45,29.71 137.2,30.96 129.67,30.96 J12.12 128.35,29.7 128.35,29.71 127.1,28.46 127.1,16.46 127.9,15.66 129.4,15.66 130.4,14.66 v131.3,14.66
  Bottom 0.254: R137.1 131.34,14.62 v131.3,14.66
DD13  (via drill 0.3 pad 0.81)
  Top 0.254: J12.14 127.75,32.21 117.2,42.76 115.6,42.76 114.03,44.33 IC23.41
  Route15 0.254: J13.14 138.4,32.26 137.15,33.51 129.68,33.51 J12.14 128.4,32.21 126.45,30.26 126.45,16.16 127.95,14.66 v129,14.66
  Bottom 0.254: R138.1 128.97,14.63 v129,14.66
DD14  (via drill 0.3 pad 0.81)
  Top 0.254: J12.16 127.45,34.76 118.05,44.16 118.05,45.66 IC23.49
  Route15 0.254: J13.16 138.4,34.81 137.2,36.01 129.64,36.01 J12.16 128.4,34.76 125.8,32.16 125.8,15.46 v126.6,14.66
  Bottom 0.254: R139.1 v126.6,14.66
DD15
  Top 0.254: J12.18 128.36,37.31 127.85,37.31 125.45,39.71 125.45,42.66 125.15,42.96 125.15,43.36 | 125.15,43.36 125.15,46.21 123.2,48.16 IC23.52 | IC23.52 | R140.1 125.22,43.33 125.15,43.36
  Route15 0.254: J12.18 129.65,38.56 137.2,38.56 138.45,37.31 138.45,37.32 J13.18
DDIR
  Top 0.254: IC21.P41 63.25,30.51 62.7,29.96 55.85,29.96 53.4,27.51 53.4,24.91 48.05,19.56 48.05,17.61 47.35,16.91 42.6,16.91 39.9,19.61 25.25,19.61 22.05,16.41 19.45,16.41 19.4,16.36 19.33,16.43 R159.2
DISP_DATA0  (via drill 0.3 pad 0.81)
  Top 0.203: 83.39,47.25 84,47.86 85.25,47.86 v85.55,47.56
  Top 0.254: IC13.21 131.35,74.96 126.15,80.16 91.25,80.16 91.2,80.26 | 91.2,80.26 91.2,81.41 86.05,86.56 84.9,86.56 84.55,86.91 84.55,88.26 84.5,88.31 84.52,88.33 SW1.1 84.52,90.29 v84.4,90.41 | IC21.P99 83.39,47.25 | v91.2,80.16 91.2,80.26
  Bottom 0.254: v84.4,90.41 84.45,90.41 84.19,90.15 R93.1 | v85.55,47.56 85.7,47.71 88.03,47.71 89.85,49.53 89.85,79.11 90.9,80.16 v91.2,80.16
DISP_DATA1  (via drill 0.3 pad 0.81)
  Top 0.254: IC13.20 131.7,75.61 126.45,80.86 93.1,80.86 v92.85,81.11 87.06,86.9 SW1.2 87.06,90.07 v87.4,90.41 | IC21.P100 83.04,47.75 83.7,48.41 87.55,48.41 v87.95,48.81
  Bottom 0.254: 86.89,88.55 86.85,88.51 | 86.89,88.55 R75.1 | v87.4,90.41 87.4,89.06 86.89,88.55 | v87.95,48.81 87.95,49.26 89.15,50.46 89.15,79.56 90.7,81.11 v92.85,81.11
DISP_DATA2  (via drill 0.3 pad 0.81)
  Top 0.254: IC13.19 132.05,76.26 126.75,81.56 94.85,81.56 v94.6,81.81 89.6,86.81 SW1.3 89.6,90.21 v89.4,90.41 | IC21.P102 83.24,48.75 83.45,48.96 85.8,48.96 v86.2,49.36
  Bottom 0.254: v89.4,90.41 89.4,90.36 89.49,90.27 R76.1 | v86.2,49.36 87,49.36 88.45,50.81 88.45,79.91 90.6,82.06 94.35,82.06 v94.6,81.81
DISP_DATA3  (via drill 0.3 pad 0.81)
  Top 0.254: IC13.18 132.4,76.91 127.05,82.26 96.25,82.26 v96,82.51 96,83.01 92.14,86.87 SW1.4 92.14,90.15 v92.4,90.41 | IC21.P103 82.89,49.25 83.45,49.81 v84.95,49.81
  Bottom 0.254: v92.4,90.41 92.45,90.41 92.24,90.2 R77.1 | v84.95,49.81 85.4,50.21 86.9,50.21 87.75,51.06 87.75,80.26 90.3,82.81 95.6,82.81 v96,82.51
DISP_DATA4  (via drill 0.3 pad 0.81)
  Top 0.254: IC13.17 132.75,77.56 127.35,82.96 97.85,82.96 v97.55,83.26 97.55,83.91 94.68,86.78 SW1.5 94.68,90.33 v94.6,90.41 | IC21.P104 82.59,49.75 83.5,50.66 85.7,50.66 v86.15,51.11
  Bottom 0.254: v94.6,90.41 94.65,90.46 94.79,90.32 R78.1 | v86.15,51.11 87.05,52.01 87.05,80.66 89.95,83.56 97.3,83.56 v97.55,83.26
DISP_DATA5  (via drill 0.3 pad 0.81)
  Top 0.254: 100.2,83.86 100.4,83.66 127.6,83.66 133.05,78.21 IC13.16 | 100.2,83.86 97.22,86.84 SW1.6 97.22,90.18 97.4,90.36 v97.4,90.41 | IC21.P105 82.24,50.25 83.35,51.36 84.65,51.36 v84.9,51.51 | v99.95,84.11 100.2,83.86
  Bottom 0.254: R79.1 97.44,90.37 v97.4,90.41 | v84.9,51.51 85.1,51.51 86.35,52.76 86.35,81.06 89.6,84.31 99.7,84.31 v99.95,84.11
DISP_DATA6  (via drill 0.3 pad 0.81)
  Top 0.254: 102.3,84.36 99.76,86.9 SW1.7 99.76,90.25 v99.6,90.41 | 102.3,84.36 127.85,84.36 133.35,78.86 IC13.15 | IC21.P107 82.34,51.25 83.8,52.71 v84.85,52.71 | 101.8,84.86 v101.85,84.81 102.3,84.36
  Bottom 0.254: R80.1 99.99,88.6 100,88.61 99.6,89.01 v99.6,90.41 | v84.85,52.71 85.1,52.71 85.65,53.26 85.65,81.41 89.3,85.06 101.55,85.06 101.8,84.81 v101.85,84.81
DISP_DATA7  (via drill 0.3 pad 0.81)
  Top 0.254: IC13.14 133.7,79.51 128.15,85.06 103.6,85.06 v103.2,85.46 103.2,85.48 102.3,86.38 SW1.8 | IC21.P108 81.94,51.75 84.1,53.91 v84.8,53.91
  Bottom 0.254: v84.8,53.91 84.95,54.06 84.95,81.71 89,85.76 103.2,85.76 103.2,85.56 | 103.2,85.56 103.2,85.73 | 103.2,85.56 v103.2,85.46 103.22,85.46 103.2,85.73 | R81.1 103.92,88.94 104.12,88.73 104.12,86.03 103.83,85.73 103.2,85.73
DISP_E1
  Top 0.254: IC21.P90 82.69,42.75 83.05,43.11 87.08,43.11 IC14.20
DISP_E2
  Top 0.254: IC21.P89 83.09,42.25 83.25,42.41 87.1,42.41 IC14.21
DISP_RS
  Top 0.254: IC21.P93 82.94,44.25 83.1,44.41 87.1,44.41 IC14.18
DISP_RW  (via drill 0.3 pad 0.81)
  Top 0.254: IC21.P92 83.04,43.75 83.1,43.71 87.1,43.71 IC14.19 89.33,43.74 89.85,44.26 89.85,46.96 90.05,47.16 90.05,48.01 89.85,48.21 89.85,49.01 90.35,49.51 v91.7,49.51 | v139.35,73.86 139.35,73.81 139.5,73.66 IC13.2
  Bottom 0.254: v91.7,49.51 96.75,44.51 96.75,36.06 99.9,32.81 105,32.81 110.4,38.21 120.3,38.21 125.05,42.96 125.05,46.21 127.6,48.76 142.9,48.76 145.65,51.51 145.65,72.36 144.2,73.86 139.4,73.86 139.35,73.91 v139.35,73.86
DMARQ
  Top 0.254: J12.21 132.13,41.16 139.1,41.16 | 139.1,41.16 139.15,41.16 | 139.1,41.16 139.71,41.16 J13.21 143.21,44.66 145.5,44.66 R119.1
FPGA_DIN  (via drill 0.3 pad 0.81)
  Top 0.254: v75.1,30.26 75.1,30.21 75.25,30.36 IC21.P65
  Bottom 0.254: IC1.1 58.1,21.66 58.74,22.3 58.74,26.85 59.5,27.61 68.4,27.61 71.2,30.41 74.95,30.41 v75.1,30.26
FPGA_INITB  (via drill 0.3 pad 0.81)
  Top 0.254: IC21.P58 71.75,29.41 v72.05,29.01 | IC23.23 103.35,48.66 99.8,45.11 v99.8,40.71
  Route15 0.254: v72.05,29.01 72.72,28.33 84.17,28.33 85.42,27.08 88.22,27.08 v88.2,27.06 | v99.8,40.71 99.2,40.71 96.5,38.01 96.5,33.93 93.78,31.21 v92.8,31.21
  Bottom 0.254: v72.05,29.01 71.7,29.01 68.9,26.21 64.75,26.21 64.4,25.86 64.4,23.16 62.65,21.41 62.65,19.91 IC1.8 62.64,19.17 62.95,18.86 65.05,18.86 65.3,19.11 65.31,19.1 R5.1 | v92.8,31.21 92.78,31.21 88.62,27.06 v88.2,27.06
GND  (via drill 0.3 pad 0.76, 0.3 pad 0.81)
